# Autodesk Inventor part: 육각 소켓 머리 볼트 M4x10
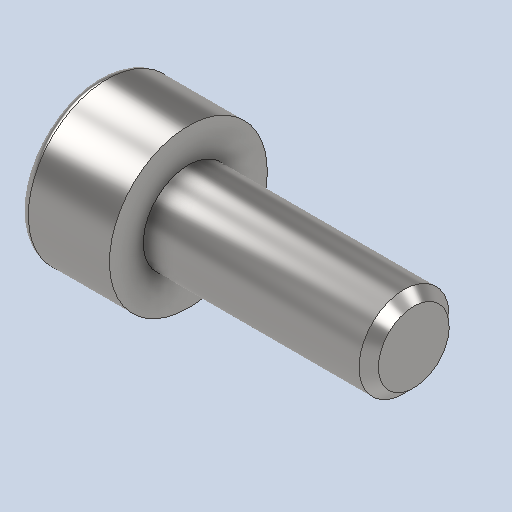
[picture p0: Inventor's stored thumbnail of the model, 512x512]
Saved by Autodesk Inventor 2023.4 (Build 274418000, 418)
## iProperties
Created: 2024-05
Part Number: 육각 소켓 머리 볼트 M4x10
Material: 강철, 연강
Description: 6각머리 태핑 나사
Document SubType Name: Modeling
Designer: edu-40
Density: 7.85 g/cm^3
Appearance: 기본값
Author: jhkim
Sending System: Autodesk Inventor 2025
Preprocessor: ST-DEVELOPER v20
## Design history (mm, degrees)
feature "Solid1"
node "솔리드1"
